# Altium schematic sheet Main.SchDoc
size A; DocumentNumber: 1; SheetNumber: 1; SheetTotal: 5
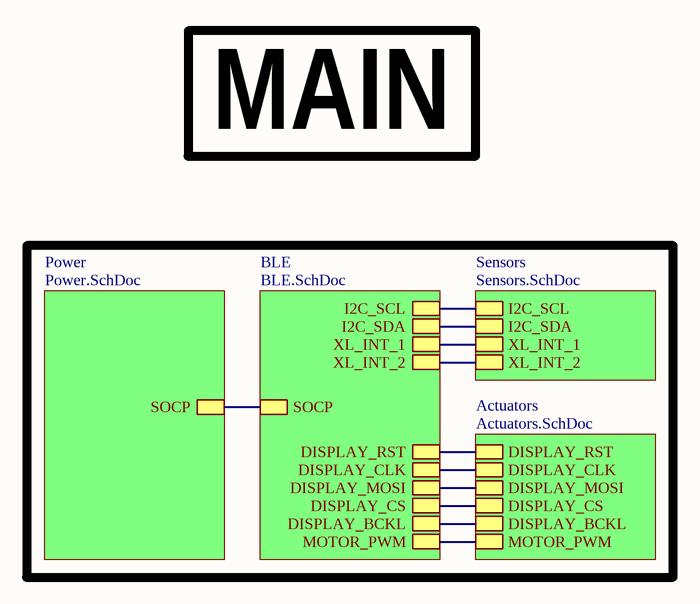
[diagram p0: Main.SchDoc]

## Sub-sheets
Actuators = Actuators.SchDoc: DISPLAY_RST, DISPLAY_CLK, DISPLAY_MOSI, DISPLAY_CS, DISPLAY_BCKL, MOTOR_PWM
BLE = BLE.SchDoc: SOCP, DISPLAY_RST, DISPLAY_CLK, DISPLAY_MOSI, DISPLAY_CS, DISPLAY_BCKL, MOTOR_PWM, I2C_SCL, I2C_SDA, XL_INT_1, XL_INT_2
Power = Power.SchDoc: SOCP
Sensors = Sensors.SchDoc: I2C_SCL, I2C_SDA, XL_INT_1, XL_INT_2

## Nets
(unnamed): sheet Power/SOCP, sheet BLE/SOCP
(unnamed): sheet Actuators/DISPLAY_RST, sheet BLE/DISPLAY_RST  [a separate net that carries the same name]
(unnamed): sheet Actuators/DISPLAY_CLK, sheet BLE/DISPLAY_CLK  [a separate net that carries the same name]
(unnamed): sheet Actuators/DISPLAY_MOSI, sheet BLE/DISPLAY_MOSI  [a separate net that carries the same name]
(unnamed): sheet Actuators/DISPLAY_CS, sheet BLE/DISPLAY_CS  [a separate net that carries the same name]
(unnamed): sheet Actuators/DISPLAY_BCKL, sheet BLE/DISPLAY_BCKL  [a separate net that carries the same name]
(unnamed): sheet Actuators/MOTOR_PWM, sheet BLE/MOTOR_PWM  [a separate net that carries the same name]
(unnamed): sheet BLE/I2C_SCL, sheet Sensors/I2C_SCL  [a separate net that carries the same name]
(unnamed): sheet BLE/I2C_SDA, sheet Sensors/I2C_SDA  [a separate net that carries the same name]
(unnamed): sheet BLE/XL_INT_1, sheet Sensors/XL_INT_1  [a separate net that carries the same name]
(unnamed): sheet BLE/XL_INT_2, sheet Sensors/XL_INT_2  [a separate net that carries the same name]

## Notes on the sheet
- MAIN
